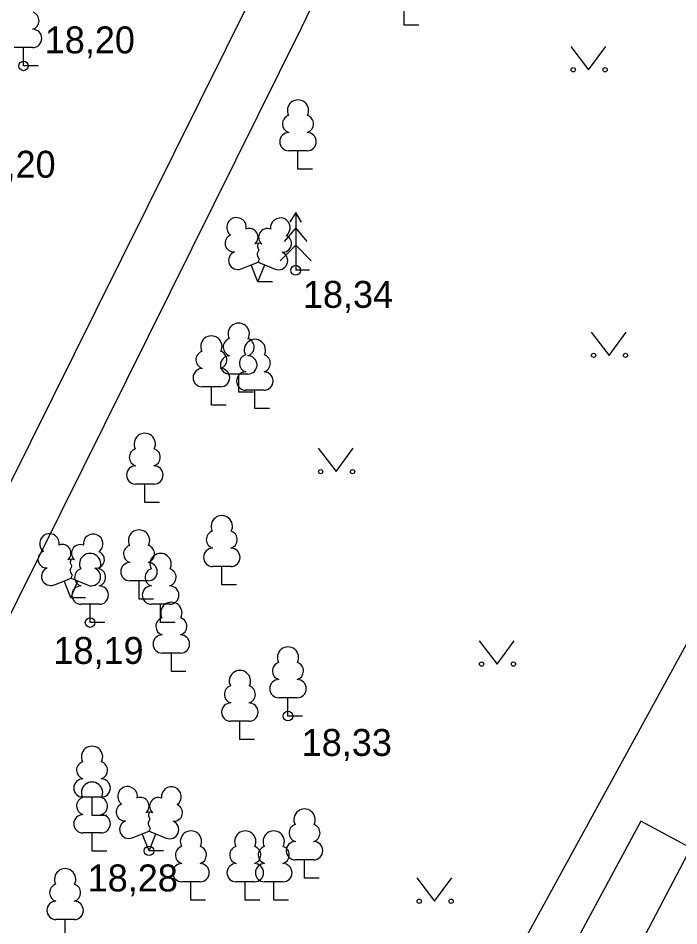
# Model space of a CAD drawing. Extents: x 713540 to 713867, y 6589774 to 6590061.
# Drawn here: x 713813.91 to 713831.07, y 6589924.79 to 6589948.37 of the extents above; entities that cross this region are included whole.
import ezdxf

# ---------------------------------------------------------------- set-up
doc = ezdxf.new("R2010")
doc.units = 0
for name, color, linetype in [('AED', 7, 'Continuous'), ('HALJASTUS', 7, 'Continuous'), ('KORGUS', 7, 'Continuous'), ('MPKAABEL', 7, 'Continuous'), ('PUU', 7, 'Continuous'), ('TEE', 7, 'Continuous'), ('VTRASS', 7, 'Continuous')]:
    doc.layers.add(name, color=color, linetype=linetype)

msp = doc.modelspace()

# ---------------------------------------------------------------- linework, layer by layer
at = {"layer": 'AED'}
msp.add_lwpolyline([(713820.28, 6589911.73), (713825.78, 6589922.08), (713837.8, 6589944.03)], dxfattribs=at)
at = {"layer": 'HALJASTUS'}
for p, q in [((713828.267, 6589947.637), (713828.73, 6589947.03)), ((713828.73, 6589947.03), (713829.176, 6589947.637)), ((713828.797, 6589940.217), (713829.26, 6589939.61)), ((713829.26, 6589939.61), (713829.706, 6589940.217)), ((713821.707, 6589937.197), (713822.17, 6589936.59)), ((713822.17, 6589936.59), (713822.616, 6589937.197)), ((713825.887, 6589932.197), (713826.35, 6589931.59)), ((713826.35, 6589931.59), (713826.796, 6589932.197)), ((713824.267, 6589926.037), (713824.73, 6589925.43)), ((713824.73, 6589925.43), (713825.176, 6589926.037))]:
    msp.add_line(p, q, dxfattribs=at)
for centre in [(713828.329, 6589947.03), (713829.158, 6589947.03), (713828.859, 6589939.61), (713829.688, 6589939.61), (713821.769, 6589936.59), (713822.598, 6589936.59), (713825.949, 6589931.59), (713826.778, 6589931.59), (713824.329, 6589925.43), (713825.158, 6589925.43)]:
    msp.add_circle(centre, 0.055, dxfattribs=at)
at = {"layer": 'KORGUS'}
for centre in [(713814.05, 6589947.13), (713821.12, 6589941.82), (713815.78, 6589932.67), (713820.92, 6589930.24), (713817.31, 6589926.74)]:
    msp.add_circle(centre, 0.125, dxfattribs=at)
at = {"layer": 'MPKAABEL'}
msp.add_lwpolyline([(713808.21, 6589921.82), (713821.27, 6589948.12), (713829.48, 6589965.13)], dxfattribs=at)
at = {"layer": 'PUU'}
for p, q in [((713823.94, 6589948.19), (713823.94, 6589948.665)), ((713824.32, 6589948.19), (713823.94, 6589948.19)), ((713814.29, 6589947.605), (713813.81, 6589947.605)), ((713814.05, 6589947.13), (713814.05, 6589947.605)), ((713814.43, 6589947.13), (713814.05, 6589947.13)), ((713821.42, 6589944.925), (713820.94, 6589944.925)), ((713821.18, 6589944.45), (713821.18, 6589944.925)), ((713821.56, 6589944.45), (713821.18, 6589944.45)), ((713821.12, 6589943.32), (713820.97, 6589943.07)), ((713821.27, 6589943.07), (713821.12, 6589943.32)), ((713821.12, 6589943.32), (713821.12, 6589941.82)), ((713821.12, 6589942.92), (713820.82, 6589942.57)), ((713821.42, 6589942.57), (713821.12, 6589942.92)), ((713821.12, 6589942.47), (713820.72, 6589942.07)), ((713821.52, 6589942.07), (713821.12, 6589942.47)), ((713819.7, 6589941.855), (713820.145, 6589942.03)), ((713820.14, 6589941.52), (713819.965, 6589941.96)), ((713820.14, 6589941.52), (713820.32, 6589941.96)), ((713820.145, 6589942.03), (713820.585, 6589941.85)), ((713821.48, 6589941.82), (713821.12, 6589941.82)), ((713820.52, 6589941.52), (713820.14, 6589941.52)), ((713819.88, 6589939.125), (713819.4, 6589939.125)), ((713819.64, 6589938.65), (713819.64, 6589939.125)), ((713819.17, 6589938.795), (713818.69, 6589938.795)), ((713818.93, 6589938.32), (713818.93, 6589938.795)), ((713820.3, 6589938.705), (713819.82, 6589938.705)), ((713820.06, 6589938.23), (713820.06, 6589938.705)), ((713820.02, 6589938.65), (713819.64, 6589938.65)), ((713819.31, 6589938.32), (713818.93, 6589938.32)), ((713820.44, 6589938.23), (713820.06, 6589938.23)), ((713817.44, 6589936.265), (713816.96, 6589936.265)), ((713817.2, 6589935.79), (713817.2, 6589936.265)), ((713817.58, 6589935.79), (713817.2, 6589935.79)), ((713819.44, 6589934.125), (713818.96, 6589934.125)), ((713819.2, 6589933.65), (713819.2, 6589934.125)), ((713814.84, 6589933.645), (713815.285, 6589933.82)), ((713815.28, 6589933.31), (713815.105, 6589933.75)), ((713815.28, 6589933.31), (713815.46, 6589933.75)), ((713815.285, 6589933.82), (713815.725, 6589933.64)), ((713817.29, 6589933.755), (713816.81, 6589933.755)), ((713817.05, 6589933.28), (713817.05, 6589933.755)), ((713819.58, 6589933.65), (713819.2, 6589933.65)), ((713815.66, 6589933.31), (713815.28, 6589933.31)), ((713817.43, 6589933.28), (713817.05, 6589933.28)), ((713816.02, 6589933.145), (713815.54, 6589933.145)), ((713815.78, 6589932.67), (713815.78, 6589933.145)), ((713817.85, 6589933.145), (713817.37, 6589933.145)), ((713817.61, 6589932.67), (713817.61, 6589933.145)), ((713816.16, 6589932.67), (713815.78, 6589932.67)), ((713817.99, 6589932.67), (713817.61, 6589932.67)), ((713818.13, 6589931.875), (713817.65, 6589931.875)), ((713817.89, 6589931.4), (713817.89, 6589931.875)), ((713818.27, 6589931.4), (713817.89, 6589931.4)), ((713821.16, 6589930.715), (713820.68, 6589930.715)), ((713820.92, 6589930.24), (713820.92, 6589930.715)), ((713821.3, 6589930.24), (713820.92, 6589930.24)), ((713819.91, 6589930.105), (713819.43, 6589930.105)), ((713819.67, 6589929.63), (713819.67, 6589930.105)), ((713820.05, 6589929.63), (713819.67, 6589929.63)), ((713816.07, 6589928.135), (713815.59, 6589928.135)), ((713815.83, 6589927.66), (713815.83, 6589928.135)), ((713816.21, 6589927.66), (713815.83, 6589927.66)), ((713816.07, 6589927.205), (713815.59, 6589927.205)), ((713815.83, 6589926.73), (713815.83, 6589927.205)), ((713816.87, 6589927.075), (713817.315, 6589927.25)), ((713817.31, 6589926.74), (713817.135, 6589927.18)), ((713817.31, 6589926.74), (713817.49, 6589927.18)), ((713817.315, 6589927.25), (713817.755, 6589927.07)), ((713816.21, 6589926.73), (713815.83, 6589926.73)), ((713817.69, 6589926.74), (713817.31, 6589926.74)), ((713821.59, 6589926.505), (713821.11, 6589926.505)), ((713821.35, 6589926.03), (713821.35, 6589926.505)), ((713818.64, 6589925.935), (713818.16, 6589925.935)), ((713818.4, 6589925.46), (713818.4, 6589925.935)), ((713820.05, 6589925.935), (713819.57, 6589925.935)), ((713819.81, 6589925.46), (713819.81, 6589925.935)), ((713820.79, 6589925.935), (713820.31, 6589925.935)), ((713820.55, 6589925.46), (713820.55, 6589925.935)), ((713821.73, 6589926.03), (713821.35, 6589926.03)), ((713818.78, 6589925.46), (713818.4, 6589925.46)), ((713820.19, 6589925.46), (713819.81, 6589925.46)), ((713820.93, 6589925.46), (713820.55, 6589925.46)), ((713815.37, 6589924.955), (713814.89, 6589924.955)), ((713815.13, 6589924.48), (713815.13, 6589924.955))]:
    msp.add_line(p, q, dxfattribs=at)
for points in [[(713820.145, 6589942.525), (713820.125, 6589942.45), (713820.125, 6589942.43), (713820.135, 6589942.4), (713820.155, 6589942.365), (713820.16, 6589942.345), (713820.145, 6589942.31), (713820.12, 6589942.26), (713820.115, 6589942.235), (713820.12, 6589942.22), (713820.13, 6589942.19), (713820.165, 6589942.13), (713820.17, 6589942.11), (713820.165, 6589942.09), (713820.15, 6589942.055), (713820.145, 6589942.03)], [(713815.285, 6589934.315), (713815.265, 6589934.24), (713815.265, 6589934.22), (713815.275, 6589934.19), (713815.295, 6589934.155), (713815.3, 6589934.135), (713815.285, 6589934.1), (713815.26, 6589934.05), (713815.255, 6589934.025), (713815.26, 6589934.01), (713815.27, 6589933.98), (713815.305, 6589933.92), (713815.31, 6589933.9), (713815.305, 6589933.88), (713815.29, 6589933.845), (713815.285, 6589933.82)], [(713817.315, 6589927.745), (713817.295, 6589927.67), (713817.295, 6589927.65), (713817.305, 6589927.62), (713817.325, 6589927.585), (713817.33, 6589927.565), (713817.315, 6589927.53), (713817.29, 6589927.48), (713817.285, 6589927.455), (713817.29, 6589927.44), (713817.3, 6589927.41), (713817.335, 6589927.35), (713817.34, 6589927.33), (713817.335, 6589927.31), (713817.32, 6589927.275), (713817.315, 6589927.25)]]:
    msp.add_lwpolyline(points, dxfattribs=at)
for centre, radius, start, end in [((713814.22, 6589948.303), 0.233, 286.8508, 70.9859), ((713814.287, 6589947.842), 0.238, 270.6047, 89.9984), ((713821.18, 6589945.97), 0.277, 332.5799, 207.4201), ((713821.01, 6589945.623), 0.233, 109.0217, 253.1415), ((713821.35, 6589945.623), 0.233, 286.8508, 70.9859), ((713820.943, 6589945.162), 0.238, 90.0016, 269.3953), ((713821.417, 6589945.162), 0.238, 270.6047, 89.9984), ((713819.583, 6589942.934), 0.256, 111.5027, 232.5173), ((713819.583, 6589942.934), 0.256, 350.4856, 111.5002), ((713820.719, 6589942.925), 0.256, 67.6168, 188.6314), ((713820.719, 6589942.925), 0.256, 306.5997, 67.6143), ((713819.918, 6589942.684), 0.224, 308.5041, 111.5725), ((713820.381, 6589942.679), 0.225, 67.7016, 230.5126), ((713819.509, 6589942.523), 0.224, 111.4304, 274.4987), ((713820.786, 6589942.513), 0.224, 264.6183, 67.6866), ((713820.144, 6589942.287), 0.237, 66.7655, 111.5015), ((713819.614, 6589942.078), 0.237, 111.5014, 291.5004), ((713820.675, 6589942.07), 0.237, 247.6166, 67.6155), ((713819.64, 6589940.17), 0.277, 332.5799, 207.4201), ((713818.93, 6589939.84), 0.277, 332.5799, 207.4201), ((713819.47, 6589939.823), 0.233, 109.0217, 253.1415), ((713820.06, 6589939.75), 0.277, 332.5799, 207.4201), ((713819.81, 6589939.823), 0.233, 286.8508, 70.9859), ((713818.76, 6589939.493), 0.233, 109.0217, 253.1415), ((713819.403, 6589939.362), 0.238, 90.0016, 269.3953), ((713819.1, 6589939.493), 0.233, 286.8508, 70.9859), ((713819.89, 6589939.403), 0.233, 109.0217, 253.1415), ((713819.877, 6589939.362), 0.238, 270.6047, 89.9984), ((713820.23, 6589939.403), 0.233, 286.8508, 70.9859), ((713818.693, 6589939.032), 0.238, 90.0016, 269.3953), ((713819.167, 6589939.032), 0.238, 270.6047, 89.9984), ((713819.823, 6589938.942), 0.238, 90.0016, 269.3953), ((713820.297, 6589938.942), 0.238, 270.6047, 89.9984), ((713817.2, 6589937.31), 0.277, 332.5799, 207.4201), ((713817.03, 6589936.963), 0.233, 109.0217, 253.1415), ((713817.37, 6589936.963), 0.233, 286.8508, 70.9859), ((713816.963, 6589936.502), 0.238, 90.0016, 269.3953), ((713817.437, 6589936.502), 0.238, 270.6047, 89.9984), ((713819.2, 6589935.17), 0.277, 332.5799, 207.4201), ((713814.723, 6589934.724), 0.256, 111.5027, 232.5173), ((713814.723, 6589934.724), 0.256, 350.4856, 111.5002), ((713815.859, 6589934.715), 0.256, 67.6168, 188.6314), ((713815.859, 6589934.715), 0.256, 306.5997, 67.6143), ((713817.05, 6589934.8), 0.277, 332.5799, 207.4201), ((713819.03, 6589934.823), 0.233, 109.0217, 253.1415), ((713819.37, 6589934.823), 0.233, 286.8508, 70.9859), ((713815.058, 6589934.474), 0.224, 308.5041, 111.5725), ((713815.521, 6589934.469), 0.225, 67.7016, 230.5126), ((713816.88, 6589934.453), 0.233, 109.0217, 253.1415), ((713817.22, 6589934.453), 0.233, 286.8508, 70.9859), ((713814.649, 6589934.313), 0.224, 111.4304, 274.4987), ((713815.78, 6589934.19), 0.277, 332.5799, 207.4201), ((713815.926, 6589934.303), 0.224, 264.6183, 67.6866), ((713817.61, 6589934.19), 0.277, 332.5799, 207.4201), ((713818.963, 6589934.362), 0.238, 90.0016, 269.3953), ((713819.437, 6589934.362), 0.238, 270.6047, 89.9984), ((713815.284, 6589934.077), 0.237, 66.7655, 111.5015), ((713816.813, 6589933.992), 0.238, 90.0016, 269.3953), ((713817.287, 6589933.992), 0.238, 270.6047, 89.9984), ((713814.754, 6589933.868), 0.237, 111.5014, 291.5004), ((713815.61, 6589933.843), 0.233, 109.0217, 253.1415), ((713815.815, 6589933.86), 0.237, 247.6166, 67.6155), ((713815.95, 6589933.843), 0.233, 286.8508, 70.9859), ((713817.44, 6589933.843), 0.233, 109.0217, 253.1415), ((713817.78, 6589933.843), 0.233, 286.8508, 70.9859), ((713815.543, 6589933.382), 0.238, 90.0016, 269.3953), ((713816.017, 6589933.382), 0.238, 270.6047, 89.9984), ((713817.373, 6589933.382), 0.238, 90.0016, 269.3953), ((713817.847, 6589933.382), 0.238, 270.6047, 89.9984), ((713817.89, 6589932.92), 0.277, 332.5799, 207.4201), ((713817.72, 6589932.573), 0.233, 109.0217, 253.1415), ((713818.06, 6589932.573), 0.233, 286.8508, 70.9859), ((713817.653, 6589932.112), 0.238, 90.0016, 269.3953), ((713818.127, 6589932.112), 0.238, 270.6047, 89.9984), ((713820.92, 6589931.76), 0.277, 332.5799, 207.4201), ((713820.75, 6589931.413), 0.233, 109.0217, 253.1415), ((713821.09, 6589931.413), 0.233, 286.8508, 70.9859), ((713819.67, 6589931.15), 0.277, 332.5799, 207.4201), ((713820.683, 6589930.952), 0.238, 90.0016, 269.3953), ((713821.157, 6589930.952), 0.238, 270.6047, 89.9984), ((713819.5, 6589930.803), 0.233, 109.0217, 253.1415), ((713819.84, 6589930.803), 0.233, 286.8508, 70.9859), ((713819.433, 6589930.342), 0.238, 90.0016, 269.3953), ((713819.907, 6589930.342), 0.238, 270.6047, 89.9984), ((713815.83, 6589929.18), 0.277, 332.5799, 207.4201), ((713815.66, 6589928.833), 0.233, 109.0217, 253.1415), ((713816, 6589928.833), 0.233, 286.8508, 70.9859), ((713815.593, 6589928.372), 0.238, 90.0016, 269.3953), ((713815.83, 6589928.25), 0.277, 332.5799, 207.4201), ((713816.067, 6589928.372), 0.238, 270.6047, 89.9984), ((713816.753, 6589928.154), 0.256, 111.5027, 232.5173), ((713816.753, 6589928.154), 0.256, 350.4856, 111.5002), ((713817.889, 6589928.145), 0.256, 67.6168, 188.6314), ((713817.889, 6589928.145), 0.256, 306.5997, 67.6143), ((713815.66, 6589927.903), 0.233, 109.0217, 253.1415), ((713816, 6589927.903), 0.233, 286.8508, 70.9859), ((713817.088, 6589927.904), 0.224, 308.5041, 111.5725), ((713817.551, 6589927.899), 0.225, 67.7016, 230.5126), ((713816.679, 6589927.743), 0.224, 111.4304, 274.4987), ((713817.956, 6589927.733), 0.224, 264.6183, 67.6866), ((713821.35, 6589927.55), 0.277, 332.5799, 207.4201), ((713815.593, 6589927.442), 0.238, 90.0016, 269.3953), ((713816.067, 6589927.442), 0.238, 270.6047, 89.9984), ((713817.314, 6589927.507), 0.237, 66.7655, 111.5015), ((713816.784, 6589927.298), 0.237, 111.5014, 291.5004), ((713817.845, 6589927.29), 0.237, 247.6166, 67.6155), ((713821.18, 6589927.203), 0.233, 109.0217, 253.1415), ((713821.52, 6589927.203), 0.233, 286.8508, 70.9859), ((713818.4, 6589926.98), 0.277, 332.5799, 207.4201), ((713819.81, 6589926.98), 0.277, 332.5799, 207.4201), ((713820.55, 6589926.98), 0.277, 332.5799, 207.4201), ((713821.113, 6589926.742), 0.238, 90.0016, 269.3953), ((713821.587, 6589926.742), 0.238, 270.6047, 89.9984), ((713818.23, 6589926.633), 0.233, 109.0217, 253.1415), ((713818.57, 6589926.633), 0.233, 286.8508, 70.9859), ((713819.64, 6589926.633), 0.233, 109.0217, 253.1415), ((713819.98, 6589926.633), 0.233, 286.8508, 70.9859), ((713820.38, 6589926.633), 0.233, 109.0217, 253.1415), ((713820.72, 6589926.633), 0.233, 286.8508, 70.9859), ((713818.163, 6589926.172), 0.238, 90.0016, 269.3953), ((713818.637, 6589926.172), 0.238, 270.6047, 89.9984), ((713819.573, 6589926.172), 0.238, 90.0016, 269.3953), ((713820.047, 6589926.172), 0.238, 270.6047, 89.9984), ((713820.313, 6589926.172), 0.238, 90.0016, 269.3953), ((713820.787, 6589926.172), 0.238, 270.6047, 89.9984), ((713815.13, 6589926), 0.277, 332.5799, 207.4201), ((713814.96, 6589925.653), 0.233, 109.0217, 253.1415), ((713815.3, 6589925.653), 0.233, 286.8508, 70.9859), ((713814.893, 6589925.192), 0.238, 90.0016, 269.3953), ((713815.367, 6589925.192), 0.238, 270.6047, 89.9984)]:
    msp.add_arc(centre, radius, start, end, dxfattribs=at)
at = {"layer": 'TEE'}
msp.add_lwpolyline([(713837.65, 6589923.45), (713830.09, 6589927.51), (713823.02, 6589914.4), (713822.18, 6589912.87), (713821.63, 6589912.28), (713820.94, 6589911.8), (713819.62, 6589911.66), (713819.17, 6589911.66), (713818.45, 6589911.73), (713817.58, 6589912.11), (713811.06, 6589915.32), (713806.01, 6589917.94), (713805.49, 6589918.43), (713805.49, 6589919.08), (713805.56, 6589919.79), (713805.76, 6589920.35), (713806.12, 6589921.05), (713809.74, 6589928.31), (713815.93, 6589940.77), (713824.03, 6589957.09)], dxfattribs=at)
at = {"layer": 'VTRASS'}
msp.add_lwpolyline([(713815.55, 6589896.63), (713834.05, 6589931.89), (713848.73, 6589924.93)], dxfattribs=at)

# ---------------------------------------------------------------- texts
at = {"layer": 'KORGUS'}
for s, p in [('18,20', (713814.601, 6589947.455)), ('18,20', (713812.541, 6589944.225)), ('18,34', (713821.308, 6589940.845)), ('18,19', (713814.826, 6589931.595)), ('18,33', (713821.276, 6589929.205)), ('18,28', (713815.716, 6589925.685))]:
    msp.add_text(s, height=0.7, dxfattribs=at).set_placement(p)

doc.saveas('drawing.dxf')
